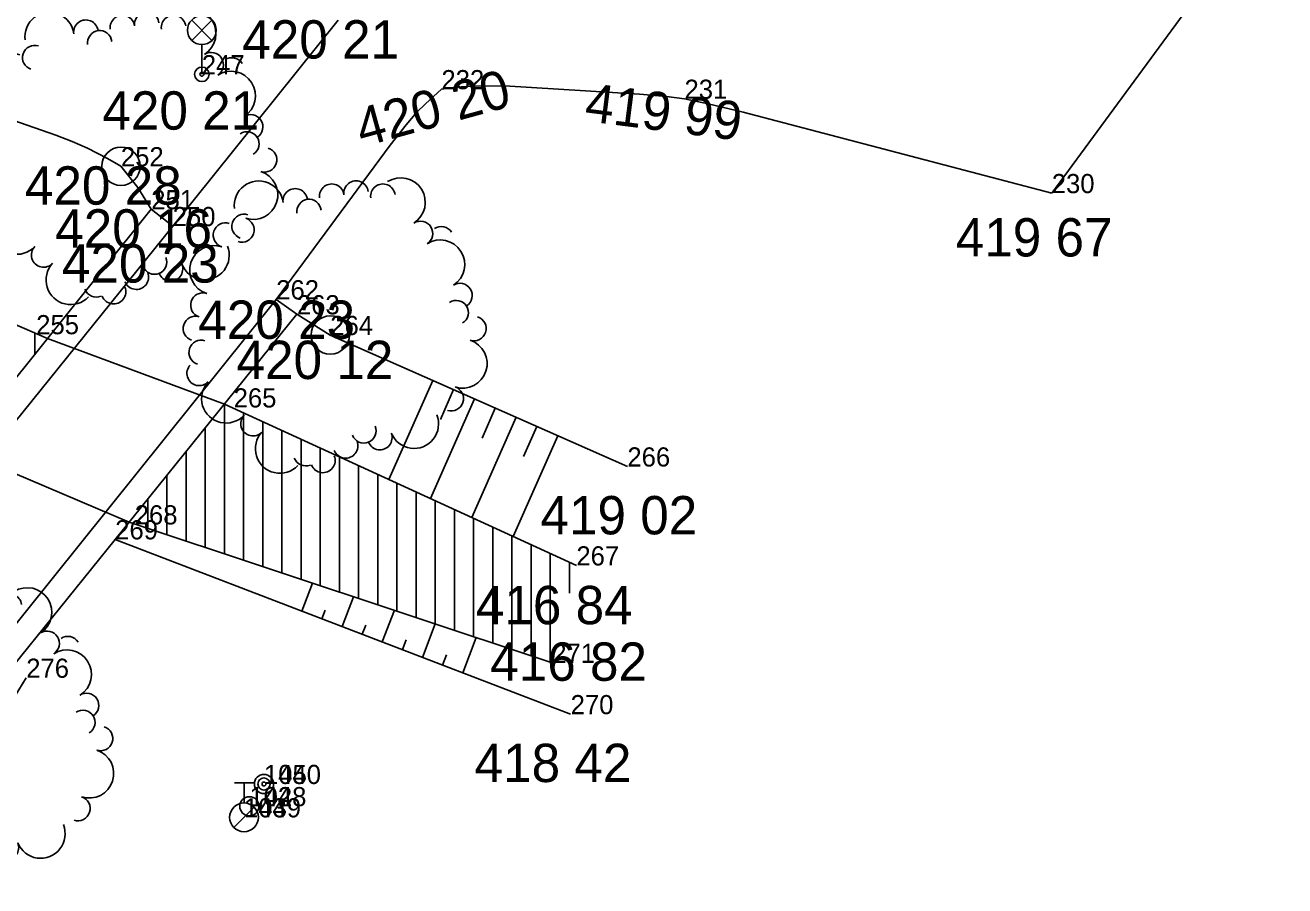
# Model space of a CAD drawing. Extents: x -559180 to -551373, y -1076947 to -1072071.
# Drawn here: x -554648.13 to -554615.27, y -1073452.46 to -1073430.02 of the extents above; entities that cross this region are included whole.
import ezdxf

# ---------------------------------------------------------------- set-up
doc = ezdxf.new("R2010")
doc.units = 0
for name, color, linetype in [('17_KOMUNIKACE', 7, 'Continuous'), ('18_POLOHOPIS', 7, 'Continuous'), ('1_VODA_ZN', 7, 'Continuous'), ('20_EL_ZN', 7, 'Continuous'), ('26_SRAFY', 7, 'Continuous'), ('27_HRANA_PATA', 7, 'Continuous'), ('28_VODA', 7, 'Continuous'), ('32', 7, 'Continuous'), ('34_ZELEN', 7, 'Continuous'), ('3_BODY', 7, 'Continuous'), ('6_VYSKY', 7, 'Continuous')]:
    doc.layers.add(name, color=color, linetype=linetype)

# ---------------------------------------------------------------- blocks, each defined once
blk = doc.blocks.new('LA')
at = {"layer": '20_EL_ZN'}
for p, q in [((-0.265, 1.415), (0.265, 0.885)), ((-0.265, 0.885), (0.265, 1.415)), ((0, 0), (0, 0.775))]:
    blk.add_line(p, q, dxfattribs=at)
for centre, radius in [((0, 1.15), 0.375), ((0, 0), 0.19), ((0, 0), 0.05)]:
    blk.add_circle(centre, radius, dxfattribs=at)
blk = doc.blocks.new('POINT_DISPLAY')
blk.add_line((0, 0), (0, 0))
blk = doc.blocks.new('STLV')
at = {"layer": '34_ZELEN'}
blk.add_circle((0, 0), 0.5, dxfattribs=at)
for centre, radius, start, end in [((-1.866, 3.377), 0.64, 7.279, 187.2791), ((0.673, 3.701), 0.32, 7.279, 187.2791), ((1.839, 3.46), 0.64, 302.4264, 122.4264), ((-0.914, 3.498), 0.32, 7.279, 187.2791), ((0.038, 3.62), 0.32, 7.279, 187.2791), ((1.372, 3.62), 0.32, 7.279, 187.2791), ((-0.552, 3.222), 0.32, 97.2791, 188.0812), ((-0.556, 3.222), 0.32, 6.4769, 97.2791), ((-2.248, 2.834), 0.32, 72.1317, 252.1317), ((2.354, 2.649), 0.32, 302.4264, 122.4264), ((-2.733, 2.607), 0.32, 72.1317, 252.1317), ((2.893, 2.511), 0.32, 32.4264, 123.2285), ((-3.027, 1.693), 0.64, 72.1317, 252.1317), ((2.869, 1.839), 0.64, 302.4264, 122.4264), ((3.383, 1.029), 0.32, 302.4264, 122.4264), ((-3.322, 0.779), 0.32, 72.1317, 252.1317), ((3.287, 0.583), 0.32, 32.4264, 123.2285), ((3.285, 0.587), 0.32, 301.6242, 32.4264), ((-3.518, 0.17), 0.32, 72.1317, 252.1317), ((3.746, 0.168), 0.32, 252.1317, 72.1317), ((-3.366, -0.453), 0.32, 72.1317, 252.1317), ((3.452, -0.746), 0.64, 252.1317, 72.1317), ((-3.419, -1.001), 0.32, 136.9844, 316.9844), ((-2.717, -1.656), 0.64, 136.9844, 316.9844), ((3.157, -1.66), 0.32, 252.1317, 72.1317), ((-2.015, -2.311), 0.32, 136.9844, 316.9844), ((2.185, -2.318), 0.64, 201.8371, 21.8371), ((-1.313, -2.966), 0.64, 136.9844, 316.9844), ((0.877, -2.497), 0.32, 201.035, 291.8371), ((0.873, -2.499), 0.32, 291.8371, 22.6393), ((1.293, -2.675), 0.32, 201.8371, 21.8371), ((0.402, -2.891), 0.32, 201.8371, 21.8371), ((-0.639, -3.093), 0.32, 201.035, 291.8371), ((-0.192, -3.27), 0.32, 201.8371, 21.8371)]:
    blk.add_arc(centre, radius, start, end, dxfattribs=at)
blk.add_blockref('POINT_DISPLAY', (0, 0), dxfattribs=at)
blk = doc.blocks.new('SV')
at = {"layer": '1_VODA_ZN'}
blk.add_circle((0, 0), 0.25, dxfattribs=at)
blk = doc.blocks.new('HYP')
at = {"layer": '1_VODA_ZN'}
for p, q in [((-0.25, 0.9), (0.25, 0.9)), ((0, 0.375), (0, 0.9)), ((-0.265, -0.265), (0.265, 0.265))]:
    blk.add_line(p, q, dxfattribs=at)
blk.add_circle((0, 0), 0.375, dxfattribs=at)
blk = doc.blocks.new('OSV')
at = {"layer": '1_VODA_ZN'}
for radius in [0.25, 0.158, 0.05]:
    blk.add_circle((0, 0), radius, dxfattribs=at)

msp = doc.modelspace()

# ---------------------------------------------------------------- linework, layer by layer
at = {"layer": '17_KOMUNIKACE'}
for p, q in [((-554611.05, -1073420.39), (-554621.35, -1073434.4)), ((-554639.96, -1073429.89), (-554644.28, -1073435.26)), ((-554644.28, -1073435.26), (-554652.63, -1073445.61)), ((-554641.58, -1073437.17), (-554649.99, -1073447.65))]:
    msp.add_line(p, q, dxfattribs=at)
for points in [[(-554637.27, -1073431.69), (-554637.688, -1073432.072), (-554637.908, -1073432.292), (-554638.188, -1073432.62), (-554638.609, -1073433.147), (-554641.58, -1073437.17)], [(-554630.93, -1073431.94), (-554631.401, -1073431.883), (-554632.105, -1073431.819), (-554635.627, -1073431.605), (-554636.487, -1073431.611), (-554636.888, -1073431.638), (-554637.27, -1073431.69)], [(-554621.35, -1073434.4), (-554629.397, -1073432.286), (-554630.314, -1073432.07), (-554630.93, -1073431.94)]]:
    msp.add_lwpolyline(points, dxfattribs=at)
at = {"layer": '18_POLOHOPIS'}
for p, q in [((-554644.84, -1073434.82), (-554653.2, -1073445.24)), ((-554644.28, -1073435.26), (-554644.84, -1073434.82)), ((-554641.58, -1073437.17), (-554641.04, -1073437.56)), ((-554641.04, -1073437.56), (-554645.78, -1073443.43)), ((-554645.78, -1073443.43), (-554649.5, -1073448.04))]:
    msp.add_line(p, q, dxfattribs=at)
at = {"layer": '26_SRAFY'}
for p, q in [((-554638.639, -1073441.869), (-554637.495, -1073439.284)), ((-554637.296, -1073440.302), (-554636.952, -1073439.524)), ((-554637.559, -1073442.364), (-554636.408, -1073439.765)), ((-554636.211, -1073440.787), (-554635.865, -1073440.005)), ((-554636.478, -1073442.859), (-554635.322, -1073440.246)), ((-554635.126, -1073441.272), (-554634.778, -1073440.486)), ((-554635.398, -1073443.354), (-554634.235, -1073440.727)), ((-554640.631, -1073444.57), (-554640.911, -1073445.299)), ((-554639.564, -1073444.925), (-554639.862, -1073445.702)), ((-554640.3, -1073445.274), (-554640.386, -1073445.5)), ((-554638.497, -1073445.28), (-554638.813, -1073446.104)), ((-554637.43, -1073445.635), (-554637.765, -1073446.507)), ((-554639.245, -1073445.663), (-554639.338, -1073445.903)), ((-554638.191, -1073446.051), (-554638.289, -1073446.305)), ((-554636.363, -1073445.99), (-554636.716, -1073446.909)), ((-554637.137, -1073446.439), (-554637.24, -1073446.708))]:
    msp.add_line(p, q, dxfattribs=at)
at = {"layer": '27_HRANA_PATA'}
for p, q in [((-554641.04, -1073437.56), (-554640.17, -1073438.1)), ((-554640.17, -1073438.1), (-554632.42, -1073441.53)), ((-554645.78, -1073443.43), (-554633.9, -1073447.99)), ((-554650.67, -1073451.22), (-554648.1, -1073447.04))]:
    msp.add_line(p, q, dxfattribs=at)
for points in [[(-554645.63, -1073433.7), (-554645.977, -1073433.498), (-554646.501, -1073433.227), (-554646.898, -1073433.051), (-554647.325, -1073432.89), (-554655.31, -1073430.11)], [(-554644.84, -1073434.82), (-554645.193, -1073434.255), (-554645.63, -1073433.7)]]:
    msp.add_lwpolyline(points, dxfattribs=at)
at = {"layer": '28_VODA'}
for p, q in [((-554656.88, -1073434.14), (-554647.544, -1073438.19)), ((-554647.544, -1073438.19), (-554642.93, -1073439.901)), ((-554642.93, -1073439.901), (-554633.75, -1073444.11)), ((-554649.869, -1073441.088), (-554645.415, -1073442.978)), ((-554645.415, -1073442.978), (-554634.38, -1073446.65))]:
    msp.add_line(p, q, dxfattribs=at)
at = {"layer": '32'}
for p, q in [((-554647.88, -1073438.609), (-554647.88, -1073438.044)), ((-554642.93, -1073443.805), (-554642.93, -1073439.901)), ((-554642.43, -1073443.971), (-554642.43, -1073440.13)), ((-554641.93, -1073444.138), (-554641.93, -1073440.359)), ((-554643.43, -1073443.639), (-554643.43, -1073440.52)), ((-554641.43, -1073444.304), (-554641.43, -1073440.589)), ((-554640.93, -1073444.47), (-554640.93, -1073440.818)), ((-554640.43, -1073444.637), (-554640.43, -1073441.047)), ((-554643.93, -1073443.472), (-554643.93, -1073441.139)), ((-554639.93, -1073444.803), (-554639.93, -1073441.276)), ((-554639.43, -1073444.97), (-554639.43, -1073441.506)), ((-554644.43, -1073443.306), (-554644.43, -1073441.758)), ((-554638.93, -1073445.136), (-554638.93, -1073441.735)), ((-554638.43, -1073445.302), (-554638.43, -1073441.964)), ((-554637.93, -1073445.469), (-554637.93, -1073442.193)), ((-554644.93, -1073443.139), (-554644.93, -1073442.377)), ((-554637.43, -1073445.635), (-554637.43, -1073442.423)), ((-554636.93, -1073445.801), (-554636.93, -1073442.652)), ((-554636.43, -1073445.968), (-554636.43, -1073442.881)), ((-554635.93, -1073446.134), (-554635.93, -1073443.11)), ((-554635.43, -1073446.301), (-554635.43, -1073443.34)), ((-554634.93, -1073446.467), (-554634.93, -1073443.569)), ((-554634.43, -1073446.633), (-554634.43, -1073443.798)), ((-554633.93, -1073444.836), (-554633.93, -1073444.027))]:
    msp.add_line(p, q, dxfattribs=at)

# ---------------------------------------------------------------- block references
at = {"layer": '1_VODA_ZN'}
for name, p in [('POINT_DISPLAY', (-554643.52, -1073431.3)), ('POINT_DISPLAY', (-554637.27, -1073431.69)), ('POINT_DISPLAY', (-554630.93, -1073431.94)), ('POINT_DISPLAY', (-554645.63, -1073433.7)), ('POINT_DISPLAY', (-554621.35, -1073434.4)), ('POINT_DISPLAY', (-554644.84, -1073434.82)), ('POINT_DISPLAY', (-554644.28, -1073435.26)), ('POINT_DISPLAY', (-554641.58, -1073437.17)), ('POINT_DISPLAY', (-554641.04, -1073437.56)), ('POINT_DISPLAY', (-554647.84, -1073438.08)), ('POINT_DISPLAY', (-554640.17, -1073438.1)), ('POINT_DISPLAY', (-554642.69, -1073439.99)), ('POINT_DISPLAY', (-554632.42, -1073441.53)), ('POINT_DISPLAY', (-554645.27, -1073443.04)), ('POINT_DISPLAY', (-554645.78, -1073443.43)), ('POINT_DISPLAY', (-554633.75, -1073444.11)), ('POINT_DISPLAY', (-554634.38, -1073446.65)), ('POINT_DISPLAY', (-554648.1, -1073447.04)), ('POINT_DISPLAY', (-554633.9, -1073447.99)), ('OSV', (-554641.9, -1073449.81)), ('HYP', (-554642.42, -1073450.68)), ('POINT_DISPLAY', (-554641.9, -1073449.81)), ('SV', (-554642.28, -1073450.39)), ('POINT_DISPLAY', (-554642.28, -1073450.39)), ('POINT_DISPLAY', (-554642.42, -1073450.68))]:
    msp.add_blockref(name, p, dxfattribs=at)
at = {"layer": '20_EL_ZN'}
msp.add_blockref('LA', (-554643.52, -1073431.3), dxfattribs=at)
at = {"layer": '34_ZELEN'}
for p in [(-554645.63, -1073433.7), (-554640.17, -1073438.1), (-554649.91, -1073448.79)]:
    msp.add_blockref('STLV', p, dxfattribs=at)

# ---------------------------------------------------------------- texts
at = {"layer": '3_BODY'}
for s, p in [('247', (-554643.52, -1073431.3)), ('232', (-554637.27, -1073431.69)), ('231', (-554630.93, -1073431.94)), ('252', (-554645.63, -1073433.7)), ('230', (-554621.35, -1073434.4)), ('251', (-554644.84, -1073434.82)), ('250', (-554644.28, -1073435.26)), ('262', (-554641.58, -1073437.17)), ('263', (-554641.04, -1073437.56)), ('255', (-554647.84, -1073438.08)), ('264', (-554640.17, -1073438.1)), ('265', (-554642.69, -1073439.99)), ('266', (-554632.42, -1073441.53)), ('268', (-554645.27, -1073443.04)), ('269', (-554645.78, -1073443.43)), ('267', (-554633.75, -1073444.11)), ('271', (-554634.38, -1073446.65)), ('276', (-554648.1, -1073447.04)), ('270', (-554633.9, -1073447.99)), ('104', (-554641.9, -1073449.81)), ('1450', (-554641.9, -1073449.81)), ('102', (-554642.28, -1073450.39)), ('1448', (-554642.28, -1073450.39)), ('103', (-554642.42, -1073450.68)), ('1449', (-554642.42, -1073450.68))]:
    msp.add_text(s, height=0.5, dxfattribs=at).set_placement(p)
at = {"layer": '6_VYSKY'}
for s, p in [('420 21', (-554642.465, -1073430.89)), ('420 21', (-554646.114, -1073432.744)), ('420 28', (-554648.135, -1073434.7)), ('420 16', (-554647.345, -1073435.82)), ('419 67', (-554623.855, -1073436.052)), ('420 23', (-554647.169, -1073436.733)), ('420 23', (-554643.612, -1073438.2)), ('420 12', (-554642.615, -1073439.248)), ('419 02', (-554634.688, -1073443.299)), ('416 84', (-554636.373, -1073445.643)), ('416 82', (-554635.999, -1073447.118)), ('418 42', (-554636.405, -1073449.759))]:
    msp.add_text(s, height=1, dxfattribs=at).set_placement(p)
for s, rotation, p in [('420 20', 15.4222, (-554639.34, -1073433.204)), ('419 99', 352.7268, (-554633.561, -1073432.515))]:
    msp.add_text(s, height=1, rotation=rotation, dxfattribs=at).set_placement(p)

doc.saveas('drawing.dxf')
